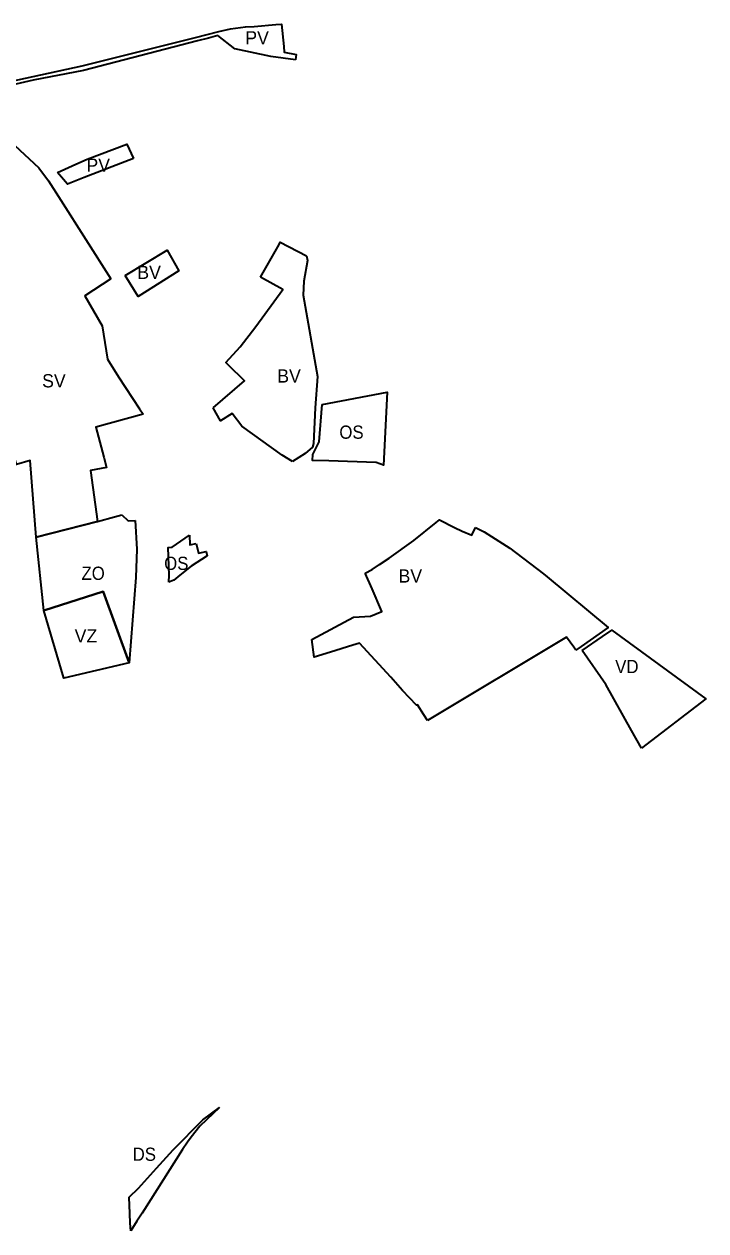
# Model space of a CAD drawing. Extents: x -650971 to -642489, y -1074311 to -1062745.
# Drawn here: x -645155 to -644537, y -1073647 to -1072552 of the extents above; entities that cross this region are included whole.
import ezdxf

# ---------------------------------------------------------------- set-up
doc = ezdxf.new("R2010")
doc.units = 0
doc.header["$LTSCALE"] = 4.8
for name, color, linetype, lineweight in [('15', 7, 'Continuous', 35), ('19', 7, 'Continuous', 35), ('24', 7, 'Continuous', 35), ('3', 7, 'Continuous', 35), ('35', 7, 'Continuous', 35), ('36', 7, 'Continuous', 35), ('42', 7, 'Continuous', 35), ('62', 7, 'Continuous', 35), ('9', 7, 'Continuous', 35)]:
    doc.layers.add(name, color=color, linetype=linetype, lineweight=lineweight)

msp = doc.modelspace()

# ---------------------------------------------------------------- linework, layer by layer
at = {"layer": '15'}
for points in [[(-645192.06, -1072609.19), (-645102.73, -1072589.74), (-644999.72, -1072564.24), (-644978.56, -1072558.74), (-644967.97, -1072556.17), (-644954.57, -1072554.43), (-644946.57, -1072554.22), (-644926.81, -1072552.51)], [(-644926.81, -1072552.51), (-644921.84, -1072552.03), (-644919.75, -1072572.43), (-644919.23, -1072577.46), (-644908.59, -1072579.51), (-644909.02, -1072584.28)], [(-644909.02, -1072584.28), (-644931.48, -1072581.26), (-644963.97, -1072574.57), (-644979.55, -1072562.44), (-644987.98, -1072564.64), (-644997.92, -1072567.23), (-645101.56, -1072594.21), (-645147.13, -1072602.79)], [(-645147.13, -1072602.79), (-645177.56, -1072609.89), (-645179.6, -1072610.94), (-645190.59, -1072616.28), (-645190.71, -1072618.6), (-645197.044, -1072612.821)], [(-645124.933, -1072686.721), (-645108.496, -1072679.193), (-645098.016, -1072674.425), (-645062.131, -1072660.856), (-645056.08, -1072674.07)], [(-645056.08, -1072674.07), (-645100.9, -1072691.31), (-645116.11, -1072697.15), (-645124.933, -1072686.721)]]:
    msp.add_lwpolyline(points, dxfattribs=at)
at = {"layer": '19'}
for points in [[(-645176.71, -1072650.01), (-645142.1, -1072682.57), (-645133.26, -1072694.17), (-645121.96, -1072711.68), (-645076.66, -1072783.06)], [(-645144.37, -1073017.64), (-645149.84, -1072948.13), (-645162.379, -1072951.55), (-645166.48, -1072936.5), (-645172.28, -1072921.42), (-645174.13, -1072877.93), (-645213.34, -1072669.98)], [(-645076.66, -1072783.06), (-645100.27, -1072798.46), (-645084.47, -1072825.67)], [(-645084.47, -1072825.67), (-645079.81, -1072855.89), (-645069.55, -1072872.12), (-645050.6, -1072901.03), (-645047.42, -1072906.05)], [(-645047.42, -1072906.05), (-645090.34, -1072917.86), (-645083.13, -1072944.94), (-645080.61, -1072954.43), (-645095.04, -1072957.07), (-645088.62, -1073003.45), (-645144.37, -1073017.64)]]:
    msp.add_lwpolyline(points, dxfattribs=at)
at = {"layer": '24'}
for points in [[(-645060.01, -1073616.531), (-645051.513, -1073608.124), (-645035.303, -1073590.199), (-645020.11, -1073573.585), (-644993.044, -1073546.324), (-644977.924, -1073535.072)], [(-644977.924, -1073535.072), (-644995.96, -1073552.09), (-645003.83, -1073561.94), (-645007.1, -1073566.62), (-645011.61, -1073573.07), (-645048.32, -1073630.82), (-645053.02, -1073638.21), (-645058.65, -1073647)], [(-645058.65, -1073647), (-645058.96, -1073640.09), (-645059.35, -1073631.3), (-645060.01, -1073616.531)]]:
    msp.add_lwpolyline(points, dxfattribs=at)
at = {"layer": '3'}
for points in [[(-644940.8, -1072781.48), (-644923.91, -1072751.94), (-644922.88, -1072749.97), (-644899.2, -1072762.14)], [(-644899.2, -1072762.14), (-644898.29, -1072766.55), (-644901.35, -1072785.36), (-644902.18, -1072797.88), (-644889.11, -1072871.66), (-644891.2, -1072900.09), (-644892.86, -1072932.6)], [(-644983.93, -1072900.24), (-644955.49, -1072875.78), (-644969.93, -1072861.43), (-644972.28, -1072859.02), (-644959.24, -1072844.92), (-644945.2, -1072826.3), (-644920.46, -1072792.92), (-644940.8, -1072781.48)], [(-644911.87, -1072948.76), (-644921.18, -1072943.17), (-644957.79, -1072916.73), (-644966.57, -1072905.23), (-644977.16, -1072912.11), (-644983.93, -1072900.24)], [(-644892.86, -1072932.6), (-644893.77, -1072935.88), (-644900.2, -1072941.67), (-644911.87, -1072948.76)], [(-644845.72, -1073050.14), (-644839.47, -1073046.89), (-644832.7, -1073042.34), (-644824.08, -1073036.56), (-644801.54, -1073020.61), (-644781.52, -1073004.39), (-644778.38, -1073001.84), (-644764.69, -1073008.87), (-644757.73, -1073012.05), (-644748.95, -1073015.64), (-644745.73, -1073008.64)], [(-644745.73, -1073008.64), (-644737.88, -1073012.62), (-644714.42, -1073027.62), (-644684.09, -1073050.8), (-644680.69, -1073053.67), (-644625.26, -1073099.51), (-644649.7, -1073116.65), (-644654.61, -1073120.1)], [(-644894.15, -1073110.3), (-644856.4, -1073090.13), (-644840.89, -1073089.3), (-644830.81, -1073084.98), (-644839.57, -1073064.5), (-644845.72, -1073050.14)], [(-644789.31, -1073183.93), (-644792.59, -1073178.73), (-644798.38, -1073169.56), (-644799.26, -1073170.13), (-644811.96, -1073156.75), (-644822.62, -1073144.71), (-644851, -1073113.77), (-644856.97, -1073115.6), (-644877.32, -1073121.83), (-644892.14, -1073126.36), (-644894.15, -1073110.3)], [(-644654.61, -1073120.1), (-644656.56, -1073117.4), (-644663.17, -1073108.27), (-644789.31, -1073183.93)]]:
    msp.add_lwpolyline(points, dxfattribs=at)
msp.add_lwpolyline([(-645063.6, -1072780.26), (-645025.61, -1072757.17), (-645015.02, -1072776.01), (-645051.94, -1072799.21)], close=True, dxfattribs=at)
at = {"layer": '35'}
for points in [[(-644648.95, -1073120.47), (-644630.58, -1073107.78), (-644622.03, -1073101.88), (-644536.62, -1073164.33), (-644595.18, -1073208.98)], [(-644595.18, -1073208.98), (-644604.13, -1073193), (-644627.53, -1073151.26), (-644648.95, -1073120.47)]]:
    msp.add_lwpolyline(points, dxfattribs=at)
at = {"layer": '36'}
msp.add_lwpolyline([(-645137.5, -1073083.97), (-645083.681, -1073066.962), (-645060.1, -1073131.68), (-645119.34, -1073145.61)], close=True, dxfattribs=at)
at = {"layer": '42'}
msp.add_line((-645144.37, -1073017.64), (-645088.62, -1073003.45), dxfattribs=at)
for points in [[(-645088.62, -1073003.45), (-645073.23, -1072999.05), (-645066.66, -1072997.3)], [(-645066.66, -1072997.3), (-645060.95, -1073002.68), (-645054.44, -1073002.54)], [(-645054.44, -1073002.54), (-645052.94, -1073028.58), (-645053.83, -1073054.04), (-645060.1, -1073131.68)], [(-645060.1, -1073131.68), (-645083.681, -1073066.962), (-645137.5, -1073083.97), (-645144.37, -1073017.64)]]:
    msp.add_lwpolyline(points, dxfattribs=at)
at = {"layer": '9'}
msp.add_line((-645023.88, -1073058.37), (-645023.6, -1073052.12), dxfattribs=at)
for points in [[(-644884.712, -1072897.147), (-644825.855, -1072886.074), (-644829.3, -1072952.16), (-644835.99, -1072949.74)], [(-644893.37, -1072942.61), (-644888.99, -1072934), (-644887.44, -1072930.94), (-644884.712, -1072897.147)], [(-644835.99, -1072949.74), (-644861.93, -1072948.94), (-644878.86, -1072948.42), (-644893.59, -1072947.97), (-644893.37, -1072942.61)], [(-645023.6, -1073052.12), (-645024.71, -1073026.95), (-645021.1, -1073026.69), (-645005.31, -1073015.68)], [(-645005.31, -1073015.68), (-645004.82, -1073024.63), (-644999.23, -1073023.29)], [(-644999.23, -1073023.29), (-644997.09, -1073032.21), (-644990.25, -1073030.54), (-644989.34, -1073034.58)], [(-644989.34, -1073034.58), (-645003.78, -1073043.96), (-645007.99, -1073047.31), (-645015.71, -1073053.41)], [(-645015.71, -1073053.41), (-645019.57, -1073056.46), (-645023.88, -1073058.37)]]:
    msp.add_lwpolyline(points, dxfattribs=at)

# ---------------------------------------------------------------- texts
at = {"layer": '62'}
for s, p in [('PV', (-644954.616, -1072570.413)), ('PV', (-645098.825, -1072686.004)), ('BV', (-645052.614, -1072783.26)), ('SV', (-645139.013, -1072881.667)), ('BV', (-644925.614, -1072877.26)), ('BV', (-644815.563, -1073058.759)), ('VZ', (-645109.496, -1073113.102))]:
    msp.add_text(s, height=12, dxfattribs=at).set_placement(p)
at = {"layer": '62', "width": 0.95}
for s, p in [('OS', (-644869.265, -1072928.272)), ('OS', (-645028.265, -1073047.272)), ('ZO', (-645103.327, -1073056.309)), ('VD', (-644618.892, -1073140.939)), ('DS', (-645056.871, -1073583.451))]:
    msp.add_text(s, height=12, dxfattribs=at).set_placement(p)

doc.saveas('drawing.dxf')
